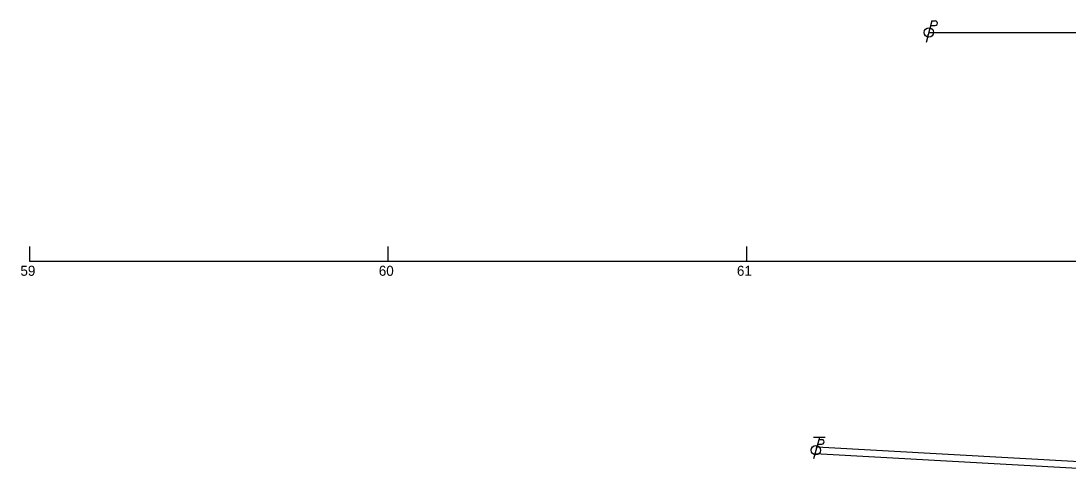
# Model space of a CAD drawing. Extents: x -2222 to 2066, y -217 to 964.
# Drawn here: x -2222.3 to -1930.2, y 778.6 to 906.5 of the extents above; entities that cross this region are included whole.
import ezdxf

# ---------------------------------------------------------------- set-up
doc = ezdxf.new("R2010")
doc.units = 0
for name, color, linetype in [('SC_Scratch1', 7, 'Continuous'), ('UT_X_Electric_Cells', 7, 'Continuous'), ('UT_X_Gas', 7, 'Continuous'), ('UT_X_Overhead_Electric', 7, 'Continuous'), ('UT_X_Overhead_Telecom', 7, 'Continuous')]:
    doc.layers.add(name, color=color, linetype=linetype)

msp = doc.modelspace()

# ---------------------------------------------------------------- linework, layer by layer
at = {"layer": 'SC_Scratch1'}
for p, q in [((-1969.38, 902.09), (-1969.21, 902.74)), ((-1968.88, 903.95), (-1968.71, 904.6)), ((-2219.84, 839.37), (-2219.84, 843.57)), ((-2119.84, 839.37), (-2119.84, 843.57)), ((-2019.84, 839.37), (-2019.84, 843.57)), ((-1914.68, 839.37), (-2219.84, 839.37)), ((-2000.9, 785.41), (-2000.72, 786.06)), ((-2000.4, 787.27), (-2000.22, 787.92))]:
    msp.add_line(p, q, dxfattribs=at)
at = {"layer": 'UT_X_Electric_Cells'}
for p, q in [((-1968.19, 906.54), (-1969.8, 900.54)), ((-1968.19, 906.54), (-1967.34, 906.54)), ((-1968.53, 905.27), (-1967.34, 905.27))]:
    msp.add_line(p, q, dxfattribs=at)
msp.add_circle((-1969.05, 903.34), 1.3, dxfattribs=at)
msp.add_arc((-1967.33, 905.91), 0.638, 268.8767, 91.1233, dxfattribs=at)
at = {"layer": 'UT_X_Gas'}
for p, q in [((-1998, 790.26), (-2001.2, 790.26)), ((-1999.6, 790.26), (-2001.2, 784.26)), ((-1999.76, 789.66), (-1998.91, 789.66)), ((-2000.1, 788.39), (-1998.91, 788.39))]:
    msp.add_line(p, q, dxfattribs=at)
msp.add_circle((-2000.56, 786.66), 1.3, dxfattribs=at)
msp.add_arc((-1998.89, 789.02), 0.638, 268.8767, 91.1233, dxfattribs=at)
at = {"layer": 'UT_X_Overhead_Electric'}
for points in [[(-1969.05, 903.34), (-1766.91, 903.34), (-1519.06, 902.65), (-1315.19, 887.1)], [(-2000.31, 787.59), (-1872.06, 780.48), (-1642.46, 791.83)]]:
    msp.add_lwpolyline(points, dxfattribs=at)
at = {"layer": 'UT_X_Overhead_Telecom'}
msp.add_lwpolyline([(-2000.81, 785.73), (-1872.55, 778.62), (-1642.96, 789.97)], dxfattribs=at)

# ---------------------------------------------------------------- texts
at = {"layer": 'SC_Scratch1'}
for s, p in [('59', (-2222.44, 835.38)), ('60', (-2122.48, 835.38)), ('61', (-2022.59, 835.38))]:
    msp.add_text(s, height=2.8, dxfattribs=at).set_placement(p)

doc.saveas('drawing.dxf')
